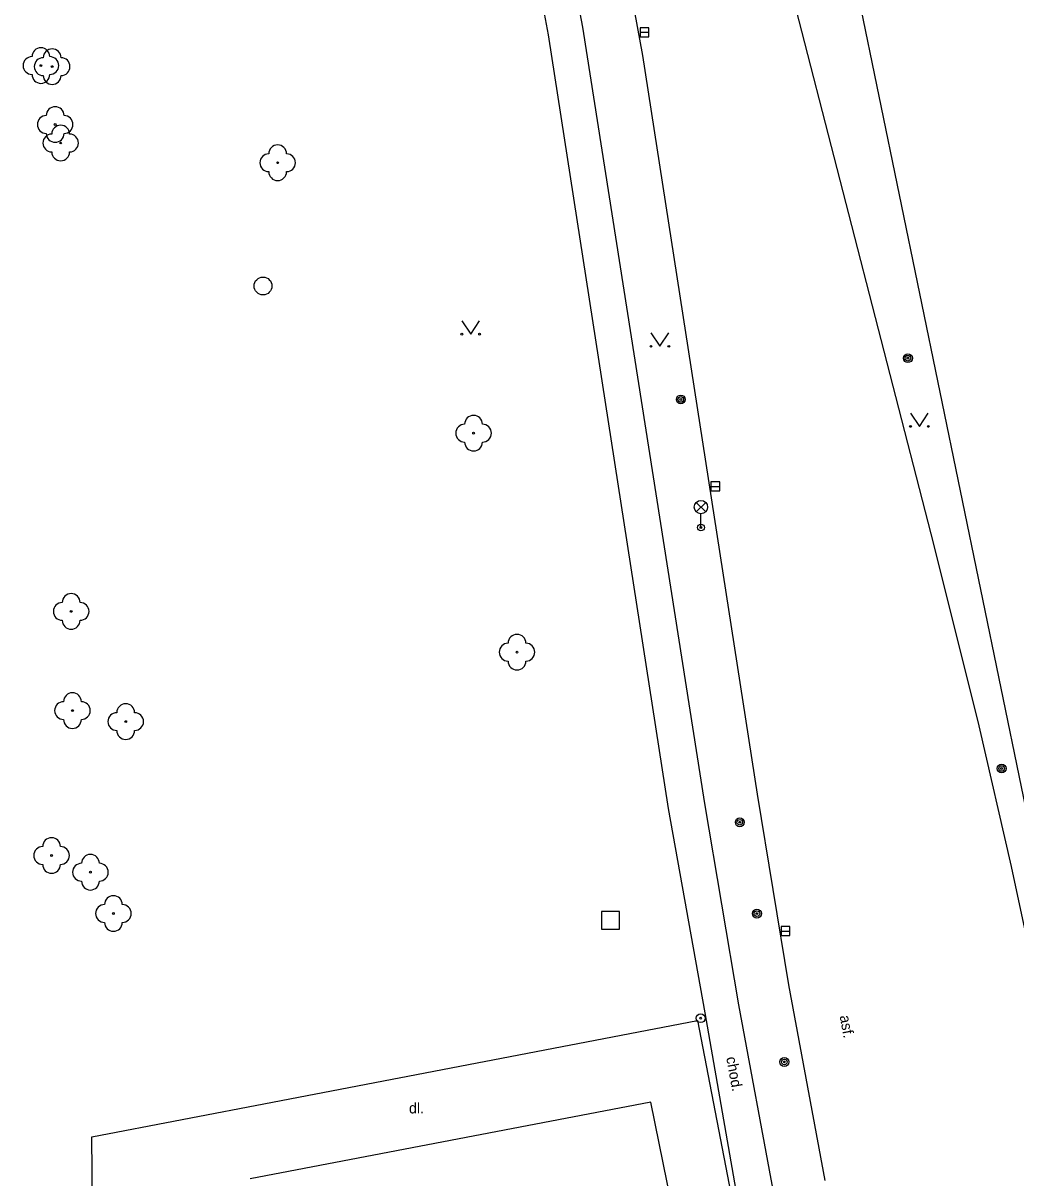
# Model space of a CAD drawing. Extents: x -640201 to -639641, y -1044739 to -1044317.
# Drawn here: x -640159.8 to -640104, y -1044553.9 to -1044489 of the extents above; entities that cross this region are included whole.
import ezdxf

# ---------------------------------------------------------------- set-up
doc = ezdxf.new("R2010")
doc.units = 0
for name, color, linetype in [('Budovy', 7, 'Continuous'), ('Ploty', 7, 'Continuous'), ('Popis povrchů', 7, 'Continuous'), ('Rozhraní ploch 1', 7, 'Continuous'), ('Sloupy_označník', 7, 'Continuous'), ('Zeleň - stromy', 7, 'Continuous'), ('Znaky doprava', 7, 'Continuous'), ('Znaky kanalizace', 7, 'Continuous'), ('Značky KM', 7, 'Continuous'), ('Šachty ner_', 7, 'Continuous')]:
    doc.layers.add(name, color=color, linetype=linetype)

msp = doc.modelspace()

# ---------------------------------------------------------------- linework, layer by layer
at = {"layer": 'Budovy'}
for p, q in [((-640124.51, -1044549.62), (-640147.01, -1044553.94)), ((-640121.86, -1044562.74), (-640124.51, -1044549.62))]:
    msp.add_line(p, q, dxfattribs=at)
at = {"layer": 'Ploty'}
for points in [[(-640145.76, -1044549.63), (-640121.9, -1044545.04)], [(-640121.9, -1044545.04), (-640118.55, -1044562.44)], [(-640155.9, -1044551.58), (-640145.76, -1044549.63)], [(-640155.84, -1044557.46), (-640155.9, -1044551.58)]]:
    msp.add_lwpolyline(points, dxfattribs=at)
at = {"layer": 'Rozhraní ploch 1'}
for p, q in [((-640101.774, -1044541.352), (-640127.52, -1044416.154)), ((-640132.19, -1044479.447), (-640130.281, -1044489.666)), ((-640128.345, -1044489.243), (-640130.099, -1044479.737)), ((-640126.954, -1044480.056), (-640124.989, -1044490.829)), ((-640117.535, -1044483.704), (-640108.638, -1044518.358)), ((-640121.494, -1044532.853), (-640128.345, -1044489.243)), ((-640130.281, -1044489.666), (-640123.544, -1044533.138)), ((-640124.989, -1044490.829), (-640118.554, -1044532.325)), ((-640108.638, -1044518.358), (-640106.102, -1044528.483)), ((-640106.102, -1044528.483), (-640104.281, -1044536.382)), ((-640118.554, -1044532.325), (-640116.788, -1044543.042)), ((-640123.544, -1044533.138), (-640121.489, -1044544.61)), ((-640119.575, -1044544.15), (-640121.494, -1044532.853)), ((-640104.281, -1044536.382), (-640101.71, -1044548.529)), ((-640116.788, -1044543.042), (-640114.749, -1044554.032)), ((-640117.613, -1044554.764), (-640119.575, -1044544.15)), ((-640121.489, -1044544.61), (-640119.614, -1044555.377))]:
    msp.add_line(p, q, dxfattribs=at)
at = {"layer": 'Sloupy_označník'}
for centre, radius in [((-640110.086, -1044507.838), 0.25), ((-640110.086, -1044507.838), 0.158), ((-640110.086, -1044507.838), 0.05), ((-640122.835, -1044510.156), 0.25), ((-640122.835, -1044510.156), 0.158), ((-640122.835, -1044510.156), 0.05), ((-640104.824, -1044530.883), 0.25), ((-640104.824, -1044530.883), 0.158), ((-640104.824, -1044530.883), 0.05), ((-640119.524, -1044533.905), 0.25), ((-640119.524, -1044533.905), 0.158), ((-640119.524, -1044533.905), 0.05), ((-640118.563, -1044539.034), 0.25), ((-640118.563, -1044539.034), 0.158), ((-640118.563, -1044539.034), 0.05), ((-640121.72, -1044544.91), 0.25), ((-640121.72, -1044544.91), 0.05), ((-640117.023, -1044547.367), 0.25), ((-640117.023, -1044547.367), 0.158), ((-640117.023, -1044547.367), 0.05)]:
    msp.add_circle(centre, radius, dxfattribs=at)
at = {"layer": 'Zeleň - stromy'}
for centre in [(-640158.76, -1044491.4), (-640158.13, -1044491.46), (-640157.96, -1044494.71), (-640157.65, -1044495.75), (-640145.47, -1044496.86), (-640134.47, -1044512.05), (-640157.06, -1044522.06), (-640132.03, -1044524.35), (-640156.99, -1044527.63), (-640154, -1044528.25), (-640158.16, -1044535.77), (-640155.98, -1044536.71), (-640154.69, -1044539.03)]:
    msp.add_circle(centre, 0.05, dxfattribs=at)
for centre, start, end in [((-640158.76, -1044490.9), 0, 180), ((-640158.13, -1044490.96), 0, 180), ((-640159.26, -1044491.4), 90, 270), ((-640158.63, -1044491.46), 90, 270), ((-640158.26, -1044491.4), 270, 90), ((-640157.63, -1044491.46), 270, 90), ((-640158.76, -1044491.9), 180, 0), ((-640158.13, -1044491.96), 180, 0), ((-640157.96, -1044494.21), 0, 180), ((-640158.46, -1044494.71), 90, 270), ((-640157.46, -1044494.71), 270, 90), ((-640157.65, -1044495.25), 0, 180), ((-640158.15, -1044495.75), 90, 270), ((-640157.96, -1044495.21), 180, 0), ((-640157.15, -1044495.75), 270, 90), ((-640157.65, -1044496.25), 180, 0), ((-640145.97, -1044496.86), 90, 270), ((-640145.47, -1044496.36), 0, 180), ((-640144.97, -1044496.86), 270, 90), ((-640145.47, -1044497.36), 180, 0), ((-640134.47, -1044511.55), 0, 180), ((-640134.97, -1044512.05), 90, 270), ((-640133.97, -1044512.05), 270, 90), ((-640134.47, -1044512.55), 180, 0), ((-640157.06, -1044521.56), 0, 180), ((-640157.56, -1044522.06), 90, 270), ((-640156.56, -1044522.06), 270, 90), ((-640157.06, -1044522.56), 180, 0), ((-640132.03, -1044523.85), 0, 180), ((-640132.53, -1044524.35), 90, 270), ((-640131.53, -1044524.35), 270, 90), ((-640132.03, -1044524.85), 180, 0), ((-640156.99, -1044527.13), 0, 180), ((-640157.49, -1044527.63), 90, 270), ((-640156.49, -1044527.63), 270, 90), ((-640154, -1044527.75), 0, 180), ((-640156.99, -1044528.13), 180, 0), ((-640154.5, -1044528.25), 90, 270), ((-640153.5, -1044528.25), 270, 90), ((-640154, -1044528.75), 180, 0), ((-640158.66, -1044535.77), 90, 270), ((-640158.16, -1044535.27), 0, 180), ((-640157.66, -1044535.77), 270, 90), ((-640155.98, -1044536.21), 0, 180), ((-640158.16, -1044536.27), 180, 0), ((-640156.48, -1044536.71), 90, 270), ((-640155.48, -1044536.71), 270, 90), ((-640155.98, -1044537.21), 180, 0), ((-640155.19, -1044539.03), 90, 270), ((-640154.69, -1044538.53), 0, 180), ((-640154.19, -1044539.03), 270, 90), ((-640154.69, -1044539.53), 180, 0)]:
    msp.add_arc(centre, 0.5, start, end, dxfattribs=at)
at = {"layer": 'Znaky doprava'}
for p, q in [((-640121.969, -1044515.934), (-640121.439, -1044516.464)), ((-640121.969, -1044516.464), (-640121.439, -1044515.934)), ((-640121.704, -1044517.349), (-640121.704, -1044516.574))]:
    msp.add_line(p, q, dxfattribs=at)
for centre, radius in [((-640121.704, -1044516.199), 0.375), ((-640121.704, -1044517.349), 0.19), ((-640121.704, -1044517.349), 0.05)]:
    msp.add_circle(centre, radius, dxfattribs=at)
at = {"layer": 'Znaky kanalizace'}
for p, q in [((-640125.123, -1044489.528), (-640124.623, -1044489.528)), ((-640121.144, -1044515.038), (-640120.644, -1044515.038)), ((-640117.206, -1044540.018), (-640116.706, -1044540.018))]:
    msp.add_line(p, q, dxfattribs=at)
for points in [[(-640125.123, -1044489.778), (-640124.623, -1044489.778), (-640124.623, -1044489.278), (-640125.123, -1044489.278)], [(-640121.144, -1044515.288), (-640120.644, -1044515.288), (-640120.644, -1044514.788), (-640121.144, -1044514.788)], [(-640117.206, -1044540.268), (-640116.706, -1044540.268), (-640116.706, -1044539.768), (-640117.206, -1044539.768)]]:
    msp.add_lwpolyline(points, close=True, dxfattribs=at)
msp.add_circle((-640146.29, -1044503.78), 0.5, dxfattribs=at)
at = {"layer": 'Značky KM'}
for p, q in [((-640135.13, -1044505.74), (-640134.63, -1044506.49)), ((-640134.63, -1044506.49), (-640134.13, -1044505.74)), ((-640124.51, -1044506.42), (-640124.01, -1044507.17)), ((-640124.01, -1044507.17), (-640123.51, -1044506.42)), ((-640109.94, -1044510.92), (-640109.44, -1044511.67)), ((-640109.44, -1044511.67), (-640108.94, -1044510.92))]:
    msp.add_line(p, q, dxfattribs=at)
for centre in [(-640135.13, -1044506.49), (-640134.13, -1044506.49), (-640124.51, -1044507.17), (-640123.51, -1044507.17), (-640109.94, -1044511.67), (-640108.94, -1044511.67)]:
    msp.add_circle(centre, 0.05, dxfattribs=at)
at = {"layer": 'Šachty ner_'}
msp.add_lwpolyline([(-640127.28, -1044539.91), (-640126.28, -1044539.91), (-640126.28, -1044538.91), (-640127.28, -1044538.91)], close=True, dxfattribs=at)

# ---------------------------------------------------------------- texts
at = {"layer": 'Popis povrchů'}
for s, rotation, p in [('asf.', 280.51071, (-640113.92, -1044544.792)), ('chod.', 280.21284, (-640120.288, -1044547.125))]:
    msp.add_text(s, height=0.6, rotation=rotation, dxfattribs=at).set_placement(p)
msp.add_text('dl.', height=0.6, dxfattribs=at).set_placement((-640138.096, -1044550.258))

doc.saveas('drawing.dxf')
